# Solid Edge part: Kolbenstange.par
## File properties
Username: ahadarics
Dokumentum tartalom típus: 0
Author: ahadarics
Last saved by: ahadarics
Revision: 78
Sűrűség: 0,000 kg/m^3
Pontosság: 0,990
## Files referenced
..\REMV 25_50.asm
\\Fsrv2\user\tervezes\Solid Edge ST4\Zylinder\Hengermodellek 2024\Körprofil R\REMV\REMV 25_50\Kit_1.par
rprofil R\REMV\REMV 25_50\Kit_1.par
rprofil R\REMV\REMV 25_50\REMV 25_50.asm
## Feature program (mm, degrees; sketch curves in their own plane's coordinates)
base feature "unnamed BaseFeature 1"
sketch for "unnamed Protrusion 1" plane through (54.5, 0, 0) normal (1, 0, 0) x-axis (0, 1, 0)
  circle centre (0, 0) radius 12.5
extrude "unnamed Protrusion 1" add to key point along -normal
thread "unnamed Thread 1"
chamfer "Letörés_1" setback 0.7
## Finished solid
Body 1: solid body, 13 faces, 23 edges, 12 vertices.
  Faces by surface: plane 9, cylinder 3, cone 1
  Edges by curve: line 12, circle 11
Bounding box of the edges (mm): 176.500 x 25.000 x 25.000, from (-122, -12.5, -12.5) to (54.5, 12.5, 12.5).
Cylindrical faces by radius (mm): R5 x2, R12.5 x1
Conical faces (half-angle, radius in mm at the cone's reference point): 45 deg R4.3 x1
Planar faces by outward normal: +x 3, +z 1, -x 4, -z 1
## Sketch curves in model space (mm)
circle centre (54.5, 0, 0) radius 12.5
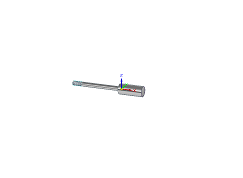
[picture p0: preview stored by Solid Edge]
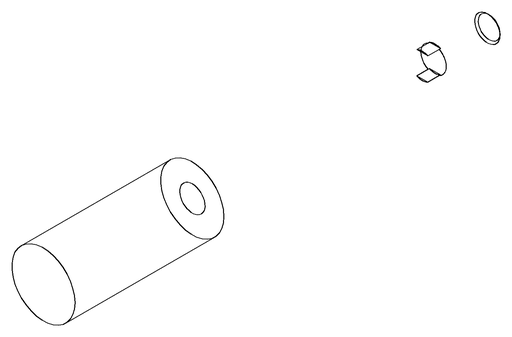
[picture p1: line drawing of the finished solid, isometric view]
